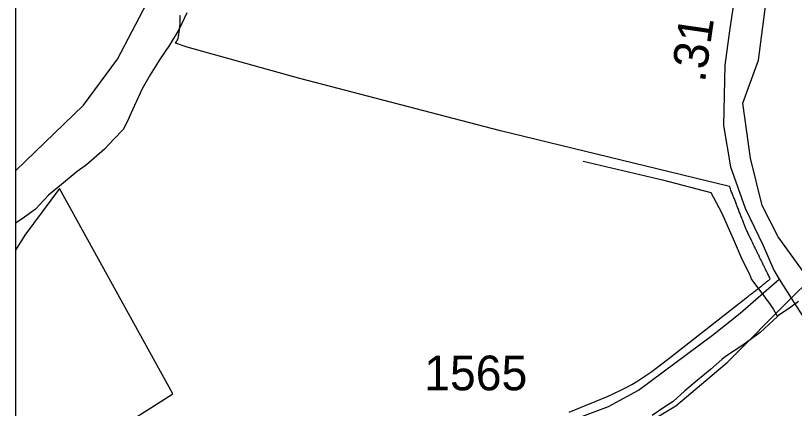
# Model space of a CAD drawing. Extents: x 2315291 to 2336543, y 597177 to 615230.
# Drawn here: x 2315744 to 2318553, y 601198 to 602614 of the extents above; entities that cross this region are included whole.
import ezdxf

# ---------------------------------------------------------------- set-up
doc = ezdxf.new("R2010")
doc.units = 0
for name, color, linetype in [('Exist Boundary Political City Limit New', 7, 'Continuous'), ('Exist Boundary Political Urban Extension UEB', 7, 'Continuous'), ('Exist Hydrographic Creek Single Shore', 7, 'Continuous'), ('Exist Hydrographic Misc Water Feature', 7, 'Continuous'), ('Exist Road Secondary Mileage Hundredths English Label', 7, 'Continuous'), ('Exist Road Secondary Type 51 Attributed', 7, 'Continuous'), ('Exist Road Secondary Type 51 Number Label', 7, 'Continuous'), ('Map Preparation Boundary City Limit Buffer Line', 7, 'Continuous')]:
    doc.layers.add(name, color=color, linetype=linetype)

msp = doc.modelspace()

# ---------------------------------------------------------------- linework, layer by layer
at = {"layer": 'Exist Boundary Political City Limit New'}
msp.add_line((2315744.5, 601767.6), (2315744.5, 599647.3), dxfattribs=at)
for points in [[(2315744.5, 604723.7), (2315744.5, 597529.5), (2327185.3, 597529.5)], [(2318415, 601769.3), (2318413.5, 601772), (2318412.2, 601774.8), (2318410.5, 601778.4), (2318408.8, 601781.9), (2318405.2, 601789.2), (2318403.5, 601792.8), (2318402.2, 601795.5), (2318401, 601798.2), (2318399.8, 601800.9), (2318398.5, 601803.6), (2318393.2, 601814.4), (2318392, 601817.1), (2318390.8, 601819.8), (2318385.5, 601830.7), (2318384, 601834.3), (2318382.2, 601838), (2318381, 601840.7), (2318379.8, 601843.4), (2318378.5, 601846.2), (2318377.5, 601848.9), (2318375.8, 601852.6), (2318374.8, 601855.4), (2318373.5, 601858.2), (2318372, 601861.9), (2318370.8, 601864.6), (2318369.8, 601867.4), (2318368.2, 601871.1), (2318366.8, 601874.9), (2318365.8, 601877.7), (2318364.5, 601880.4), (2318363.2, 601884.2), (2318361.8, 601887.9), (2318360.2, 601891.6), (2318358.8, 601895.4), (2318357.5, 601899.1), (2318356, 601902.8), (2318354.5, 601906.6), (2318353.5, 601909.4), (2318352.5, 601912.2), (2318351.2, 601916), (2318349.8, 601919.8), (2318348.5, 601923.5), (2318347.2, 601926.3), (2318346.2, 601929.1), (2318345, 601932.9), (2318343.5, 601936.6), (2318342, 601940.4), (2318341, 601943.2), (2318340, 601945.9), (2318338.5, 601949.7), (2318337, 601953.4), (2318335.2, 601957.1), (2318334.2, 601959.8), (2318333, 601962.6), (2318331.5, 601966.3), (2318330, 601970), (2318328.5, 601973.8), (2318327, 601977.4), (2318325.5, 601981.2), (2318324.2, 601984.9), (2318322.8, 601988.6), (2318321.5, 601992.4), (2318320.5, 601995.2), (2318319.8, 601997), (2317493.8, 602198.1), (2316764.5, 602387.5), (2316363.2, 602500), (2316321.5, 602514.1), (2316323.5, 602517.9), (2316325.5, 602521.7), (2316328, 602526.4), (2316330.5, 602531.8), (2316332, 602537.4), (2316332.5, 602540.3), (2316333, 602543.2), (2316333.8, 602548.2), (2316334.2, 602553.1), (2316334.8, 602557), (2316335.2, 602560), (2316335.5, 602562.9), (2316336.2, 602568.5), (2316336.8, 602572.8), (2316337.2, 602576.7), (2316337.8, 602580.6), (2316338.2, 602584.9), (2316338.5, 602590.6), (2316338.5, 602596.6), (2316338.2, 602600), (2316338.2, 602603.9), (2316337.8, 602607.6), (2316337.5, 602610.5), (2316337.2, 602614.4)], [(2315921.8, 601002.4), (2316312.2, 601250.2), (2315902.8, 601990.2), (2315778, 601821.9), (2315744.5, 601767.6)], [(2317740.8, 601184.1), (2317801.8, 601209.1), (2317834.5, 601222.4), (2317881.5, 601242.2), (2317901.8, 601251.2), (2317927, 601262.9), (2317948.8, 601274.3), (2317967.5, 601284.4), (2317988.8, 601297), (2318014, 601313.6), (2318039, 601331.2), (2318070, 601354.3), (2318100.8, 601377.8), (2318384.5, 601599.6), (2318387, 601601.6), (2318390.2, 601604.1), (2318393.2, 601606.6), (2318396.5, 601609), (2318398.8, 601610.9), (2318401.2, 601612.8), (2318404.2, 601615.2), (2318407.5, 601617.7), (2318410.5, 601620.2), (2318413.8, 601622.7), (2318416.8, 601625.2), (2318420, 601627.6), (2318423, 601630.1), (2318426.2, 601632.6), (2318429.2, 601635.1), (2318435.8, 601640.1), (2318438.8, 601642.5), (2318442, 601645), (2318445, 601647.5), (2318448.2, 601650), (2318451.2, 601652.4), (2318454.5, 601654.9), (2318456.8, 601656.8), (2318459.2, 601658.7), (2318462.2, 601661.1), (2318465.5, 601665), (2318464.2, 601667.8), (2318463, 601670.4), (2318461.2, 601674), (2318459.5, 601677.6), (2318457.8, 601681.2), (2318456, 601684.8), (2318452.5, 601692), (2318450.8, 601695.6), (2318449, 601699.2), (2318447.8, 601701.9), (2318446.2, 601704.6), (2318445, 601707.2), (2318443.8, 601710), (2318442.5, 601712.7), (2318441.2, 601715.4), (2318439.5, 601719), (2318437.8, 601722.6), (2318434.2, 601729.8), (2318433, 601732.5), (2318431.5, 601735.2), (2318430.2, 601737.9), (2318429, 601740.6), (2318427.5, 601743.2), (2318426.2, 601746), (2318424.5, 601749.6), (2318423.2, 601752.2), (2318422, 601754.9), (2318420.5, 601757.7), (2318419.2, 601760.4), (2318418, 601763.1), (2318416.8, 601765.8), (2318415, 601769.3)]]:
    msp.add_lwpolyline(points, dxfattribs=at)
at = {"layer": 'Exist Boundary Political Urban Extension UEB'}
for points in [[(2318542.1, 601594.9), (2318607.6, 601660.5), (2318494.4, 601816.2), (2318437.7, 601929.5), (2318395.3, 602099.4), (2318366.9, 602297.6), (2318423.6, 602453.3), (2318451.9, 602665.7), (2318494.4, 602906.3), (2318466, 603090.4), (2318423.6, 603175.3), (2318692.6, 603345.2), (2318735.1, 603387.7), (2318848.4, 603600.1), (2319238.3, 604375.7)], [(2317638.9, 601007.3), (2317857.2, 601080), (2317984.6, 601122.5), (2318126.2, 601207.5), (2318310.3, 601363.2), (2318542.1, 601594.9)]]:
    msp.add_lwpolyline(points, dxfattribs=at)
at = {"layer": 'Exist Hydrographic Creek Single Shore'}
msp.add_lwpolyline([(2315744.5, 602054.5), (2315989.3, 602291.1), (2316112.3, 602456.9), (2316218.3, 602658.1), (2316316.3, 602868.8), (2316445.3, 603235), (2316500.2, 603588.3), (2316583.3, 604336.6), (2316666.1, 605186.6), (2316690.1, 605279.5), (2316697.3, 605388), (2316981.3, 606075.5), (2317204.2, 606258.5), (2317425.2, 606522.7)], dxfattribs=at)
at = {"layer": 'Exist Hydrographic Misc Water Feature'}
for points in [[(2316362, 602623.3), (2316335, 602565), (2316299.3, 602506.6), (2316265.7, 602458.2), (2316230.4, 602399.8), (2316200.9, 602349.5), (2316173.8, 602289.5), (2316161.9, 602263.3), (2316148.4, 602232.9), (2316132.2, 602202.9), (2316099, 602168.6), (2316065.7, 602132.2), (2315999.7, 602075.7), (2315966.3, 602051.1), (2315910.5, 602004.7), (2315862.9, 601966.1), (2315816, 601916), (2315768, 601881.4), (2315744.5, 601865.7)], [(2317791.3, 602088.6), (2318077.7, 602022), (2318251.8, 601975.9), (2318291, 601904.3), (2318332, 601808.5), (2318364.4, 601733.1), (2318391.2, 601681.7), (2318399.2, 601661.8), (2318432, 601617.9), (2318466.1, 601572.2), (2318478.4, 601554.5), (2318492.3, 601528.5)], [(2318568.2, 601583.2), (2318540.1, 601563.1), (2318496.4, 601532.8), (2318492.3, 601528.5)], [(2318492.3, 601528.5), (2318429.4, 601471.9), (2318367.7, 601425.2), (2318304.3, 601384.8), (2318292, 601374.5), (2318250.8, 601338.2), (2318203.2, 601297.9), (2318157.7, 601261.4), (2318115.9, 601222.7), (2318082.4, 601200.5), (2318040.6, 601171.9)]]:
    msp.add_lwpolyline(points, dxfattribs=at)
at = {"layer": 'Exist Road Secondary Type 51 Attributed'}
for points in [[(2318290.6, 603260.6), (2318319.2, 603175.8), (2318343.9, 603090), (2318359.2, 602989), (2318359.2, 602880.4), (2318349.7, 602760.3), (2318319.2, 602558.3), (2318302, 602434.4), (2318297.3, 602217.8), (2318323, 602068.5), (2318376.3, 601919.8), (2318441.1, 601784.5), (2318479.2, 601695.9), (2318498.2, 601663.5)], [(2315744.5, 600095.6), (2316689.5, 600626.2), (2317256.4, 600939.2), (2317454.5, 601038.4), (2317675.4, 601126), (2317883, 601204.2), (2317991.6, 601263.2), (2318258.2, 601461.5), (2318357.3, 601541.5), (2318498.2, 601663.5)], [(2318498.2, 601663.5), (2318542.1, 601594.9), (2318660.7, 601409.7), (2318820.7, 601214.7), (2318885.4, 601114.3), (2318927.3, 601036.8), (2318961.6, 600970.7), (2319008.2, 600873.1), (2319051.3, 600756.2), (2319090.9, 600617.6), (2319100.2, 600571.4), (2319144.5, 600351.3), (2319197.8, 600111.2), (2319253, 599927.3), (2319300.4, 599837.8), (2319321.6, 599790.1), (2319355.9, 599740.5), (2319403.5, 599670), (2319477.8, 599578.5), (2319616.8, 599450.8), (2319723.5, 599353.6), (2319780.6, 599306), (2319817.5, 599280.1), (2319875.9, 599227.8)]]:
    msp.add_lwpolyline(points, dxfattribs=at)
at = {"layer": 'Map Preparation Boundary City Limit Buffer Line'}
msp.add_line((2315744.5, 601767.6), (2315744.5, 599647.3), dxfattribs=at)
for points in [[(2315744.5, 604723.7), (2315744.5, 597529.5), (2327185.3, 597529.5)], [(2318415, 601769.3), (2318413.5, 601772), (2318412.2, 601774.8), (2318410.5, 601778.4), (2318408.8, 601781.9), (2318405.2, 601789.2), (2318403.5, 601792.8), (2318402.2, 601795.5), (2318401, 601798.2), (2318399.8, 601800.9), (2318398.5, 601803.6), (2318393.2, 601814.4), (2318392, 601817.1), (2318390.8, 601819.8), (2318385.5, 601830.7), (2318384, 601834.3), (2318382.2, 601838), (2318381, 601840.7), (2318379.8, 601843.4), (2318378.5, 601846.2), (2318377.5, 601848.9), (2318375.8, 601852.6), (2318374.8, 601855.4), (2318373.5, 601858.2), (2318372, 601861.9), (2318370.8, 601864.6), (2318369.8, 601867.4), (2318368.2, 601871.1), (2318366.8, 601874.9), (2318365.8, 601877.7), (2318364.5, 601880.4), (2318363.2, 601884.2), (2318361.8, 601887.9), (2318360.2, 601891.6), (2318358.8, 601895.4), (2318357.5, 601899.1), (2318356, 601902.8), (2318354.5, 601906.6), (2318353.5, 601909.4), (2318352.5, 601912.2), (2318351.2, 601916), (2318349.8, 601919.8), (2318348.5, 601923.5), (2318347.2, 601926.3), (2318346.2, 601929.1), (2318345, 601932.9), (2318343.5, 601936.6), (2318342, 601940.4), (2318341, 601943.2), (2318340, 601945.9), (2318338.5, 601949.7), (2318337, 601953.4), (2318335.2, 601957.1), (2318334.2, 601959.8), (2318333, 601962.6), (2318331.5, 601966.3), (2318330, 601970), (2318328.5, 601973.8), (2318327, 601977.4), (2318325.5, 601981.2), (2318324.2, 601984.9), (2318322.8, 601988.6), (2318321.5, 601992.4), (2318320.5, 601995.2), (2318319.8, 601997), (2317493.8, 602198.1), (2316764.5, 602387.5), (2316363.2, 602500), (2316321.5, 602514.1), (2316323.5, 602517.9), (2316325.5, 602521.7), (2316328, 602526.4), (2316330.5, 602531.8), (2316332, 602537.4), (2316332.5, 602540.3), (2316333, 602543.2), (2316333.8, 602548.2), (2316334.2, 602553.1), (2316334.8, 602557), (2316335.2, 602560), (2316335.5, 602562.9), (2316336.2, 602568.5), (2316336.8, 602572.8), (2316337.2, 602576.7), (2316337.8, 602580.6), (2316338.2, 602584.9), (2316338.5, 602590.6), (2316338.5, 602596.6), (2316338.2, 602600), (2316338.2, 602603.9), (2316337.8, 602607.6), (2316337.5, 602610.5), (2316337.2, 602614.4)], [(2315921.8, 601002.4), (2316312.2, 601250.2), (2315902.8, 601990.2), (2315778, 601821.9), (2315744.5, 601767.6)], [(2317740.8, 601184.1), (2317801.8, 601209.1), (2317834.5, 601222.4), (2317881.5, 601242.2), (2317901.8, 601251.2), (2317927, 601262.9), (2317948.8, 601274.3), (2317967.5, 601284.4), (2317988.8, 601297), (2318014, 601313.6), (2318039, 601331.2), (2318070, 601354.3), (2318100.8, 601377.8), (2318384.5, 601599.6), (2318387, 601601.6), (2318390.2, 601604.1), (2318393.2, 601606.6), (2318396.5, 601609), (2318398.8, 601610.9), (2318401.2, 601612.8), (2318404.2, 601615.2), (2318407.5, 601617.7), (2318410.5, 601620.2), (2318413.8, 601622.7), (2318416.8, 601625.2), (2318420, 601627.6), (2318423, 601630.1), (2318426.2, 601632.6), (2318429.2, 601635.1), (2318435.8, 601640.1), (2318438.8, 601642.5), (2318442, 601645), (2318445, 601647.5), (2318448.2, 601650), (2318451.2, 601652.4), (2318454.5, 601654.9), (2318456.8, 601656.8), (2318459.2, 601658.7), (2318462.2, 601661.1), (2318465.5, 601665), (2318464.2, 601667.8), (2318463, 601670.4), (2318461.2, 601674), (2318459.5, 601677.6), (2318457.8, 601681.2), (2318456, 601684.8), (2318452.5, 601692), (2318450.8, 601695.6), (2318449, 601699.2), (2318447.8, 601701.9), (2318446.2, 601704.6), (2318445, 601707.2), (2318443.8, 601710), (2318442.5, 601712.7), (2318441.2, 601715.4), (2318439.5, 601719), (2318437.8, 601722.6), (2318434.2, 601729.8), (2318433, 601732.5), (2318431.5, 601735.2), (2318430.2, 601737.9), (2318429, 601740.6), (2318427.5, 601743.2), (2318426.2, 601746), (2318424.5, 601749.6), (2318423.2, 601752.2), (2318422, 601754.9), (2318420.5, 601757.7), (2318419.2, 601760.4), (2318418, 601763.1), (2318416.8, 601765.8), (2318415, 601769.3)]]:
    msp.add_lwpolyline(points, dxfattribs=at)

# ---------------------------------------------------------------- texts
at = {"layer": 'Exist Road Secondary Mileage Hundredths English Label'}
msp.add_text('.31', height=125, rotation=81.7228, dxfattribs=at).set_placement((2318230.3, 602370))
at = {"layer": 'Exist Road Secondary Type 51 Number Label'}
msp.add_text('1565', height=125, dxfattribs=at).set_placement((2317218.2, 601263))

doc.saveas('drawing.dxf')
